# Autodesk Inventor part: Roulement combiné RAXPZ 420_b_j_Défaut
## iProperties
Shininess: 64.0
Length Units: 11269
Angle Units: 11279
Time Units: 11290
Mass Units: 11283
Length Display Precision: 3
Angle Display Precision: 2
Compacted: True
Part Number: Roulement combiné RAXPZ 420_b_j_Défaut
Document SubType Name: Modeling
Created: 2006-01
Material: Par défaut
Designer: riri
Density: 0.0
Volumn: 0.0
Area: 0.0
PropertySet Name: Model Information
Control State: 0
Master: False
Checked Out: False
Author: riri
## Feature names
1. Base1
